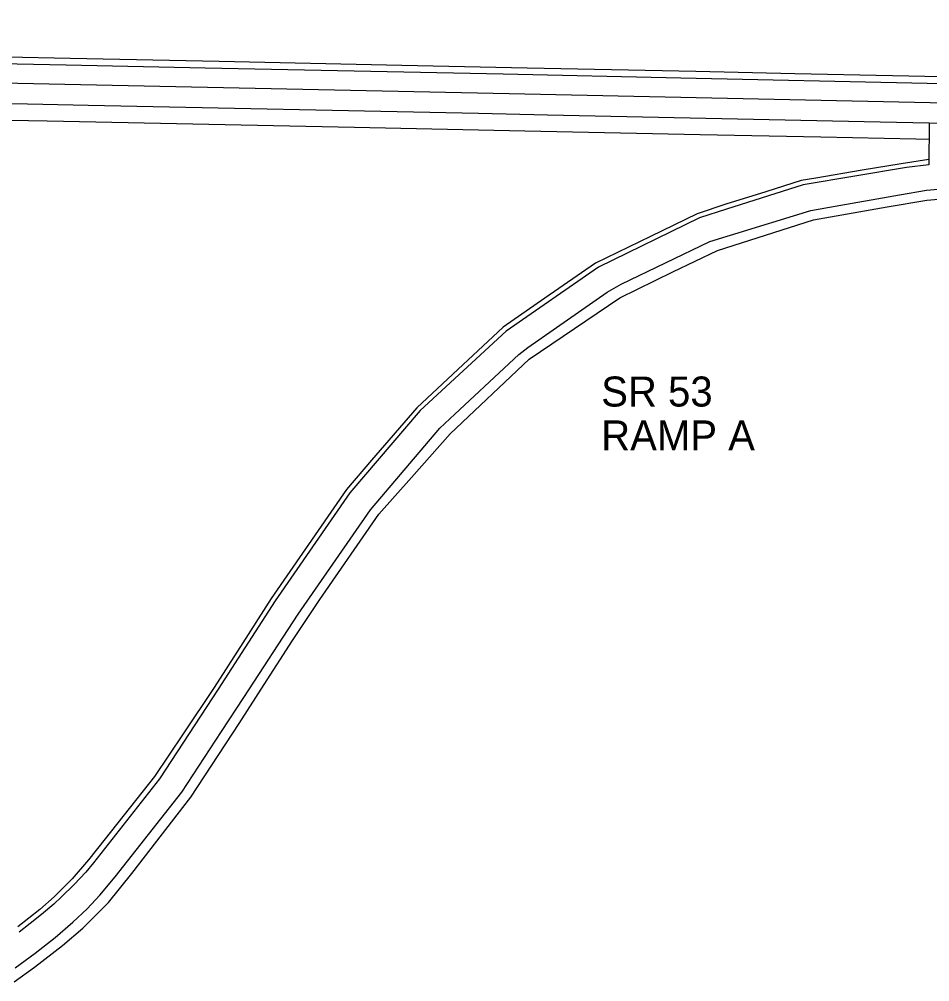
# Model space of a CAD drawing. Extents: x 1855721 to 1876784, y 662259 to 674089.
# Drawn here: x 1870534 to 1871080, y 669683 to 670260 of the extents above; entities that cross this region are included whole.
import ezdxf

# ---------------------------------------------------------------- set-up
doc = ezdxf.new("R2010")
doc.units = 0
for name, color, linetype in [('_CIVIL_CONSTRUCTION', 7, 'Continuous'), ('GE_X_Alignment_100_Bearings', 7, 'Continuous'), ('GE_X_Alignment_100_Cardinal_Points', 7, 'Continuous'), ('GE_X_Alignment_100_Curve_Data', 7, 'Continuous'), ('SC_Scratch1', 7, 'Continuous')]:
    doc.layers.add(name, color=color, linetype=linetype)

msp = doc.modelspace()

# ---------------------------------------------------------------- linework, layer by layer
at = {"layer": '_CIVIL_CONSTRUCTION'}
msp.add_line((1871080.01, 670198.03), (1871079.66, 670172.78), dxfattribs=at)
for points in [[(1870234.8, 670215.72), (1870277.14, 670214.96), (1870306.82, 670214.43), (1870547.81, 670209.13), (1870575.11, 670208.54), (1870809.46, 670203.68), (1870850.75, 670202.82), (1871050.46, 670198.65), (1871080.01, 670198.03)], [(1870531.36, 669690.95), (1870543.28, 669699.65), (1870555.2, 669709.02), (1870565.87, 669718.21), (1870574.44, 669726.36), (1870582.1, 669734.43), (1870591.38, 669745.56), (1870631.32, 669796.32), (1870655.2, 669832.74), (1870668.53, 669853.09), (1870701.24, 669903.1), (1870744.61, 669965.8), (1870786.27, 670014.74), (1870795.16, 670023.11), (1870833.58, 670058.85), (1870839, 670063.18), (1870886.58, 670096.44), (1870895.04, 670101.16), (1870948.3, 670126.73), (1870960.63, 670130.57), (1871008.85, 670145.44), (1871020.17, 670147.43), (1871062.04, 670154.79), (1871078.4, 670157.49), (1871099.34, 670159.4)]]:
    msp.add_lwpolyline(points, dxfattribs=at)
at = {"layer": 'GE_X_Alignment_100_Bearings'}
msp.add_lwpolyline([(1869304.01, 670248.74), (1869402.4, 670246.63), (1869701.27, 670239.83), (1869838.6, 670236.8), (1869901.39, 670235.7), (1870061.29, 670232.32), (1870306.95, 670226.64), (1870570.41, 670220.93), (1870827.85, 670215.6), (1871080.56, 670210.16), (1871438.65, 670202.48), (1871763.97, 670195.25), (1872009.16, 670190.02), (1872201.36, 670186.27), (1872386.22, 670182.41), (1872671.76, 670176.66)], dxfattribs=at)
at = {"layer": 'GE_X_Alignment_100_Cardinal_Points'}
msp.add_line((1871080.01, 670198.03), (1871766.97, 670183.37), dxfattribs=at)
at = {"layer": 'GE_X_Alignment_100_Curve_Data'}
for points in [[(1869312.19, 670260.13), (1869356.66, 670259.09), (1869411.58, 670257.82), (1869662.96, 670252.5), (1869704.1, 670251.62), (1869832.77, 670248.6), (1869881.61, 670247.5), (1869917.95, 670246.72), (1870016.19, 670244.73), (1870072.19, 670243.57), (1870302.52, 670238.15), (1870374.92, 670236.63), (1870561.95, 670232.73), (1870645.26, 670231.01), (1870824.17, 670227.32), (1870930.78, 670225.03), (1871078.75, 670221.85), (1871163.65, 670220.03)], [(1871079.66, 670172.78), (1871066.4, 670171.09), (1871004.21, 670160.82), (1870958.33, 670146.25), (1870942.02, 670140.99), (1870881.42, 670111.38), (1870826.01, 670072.97), (1870774.37, 670025.27), (1870732.11, 669975.85), (1870687.32, 669911.21), (1870653.21, 669858.14), (1870617.82, 669804.32), (1870578.24, 669753.91), (1870573.61, 669748.29), (1870566.78, 669740.82), (1870559.18, 669733.38), (1870554.46, 669729.1), (1870547.11, 669722.85), (1870540.37, 669717.44), (1870533.68, 669712.32)]]:
    msp.add_lwpolyline(points, dxfattribs=at)
at = {"layer": 'SC_Scratch1'}
for points in [[(1869971.04, 670249.82), (1870035.68, 670248.42), (1870088.03, 670247.25), (1870147.03, 670245.9), (1870222.18, 670244.18), (1870286.43, 670242.7), (1870374.51, 670240.81), (1870487.6, 670238.42), (1870564.28, 670236.8), (1870653.78, 670234.91), (1870763.31, 670232.61), (1870838.63, 670231.02), (1870939.83, 670228.88), (1870999.36, 670227.62), (1871057.84, 670226.39), (1871116.3, 670225.15)], [(1870234.49, 670203.93), (1870270.24, 670204.08), (1870550.58, 670199.25), (1870734.97, 670195.37), (1870837.14, 670193.22), (1870942.52, 670191.05), (1871014.97, 670189.55), (1871071.82, 670188.37), (1871079.87, 670188.21)], [(1871079.7, 670176.01), (1871063.1, 670173.39), (1871039.73, 670169.5), (1871011.79, 670164.85), (1871003.01, 670163.33), (1870981.93, 670156.65), (1870957.95, 670149.06), (1870940.59, 670143.42), (1870912.68, 670129.85), (1870879.7, 670113.81), (1870849.23, 670092.66), (1870824.17, 670075.26), (1870794.08, 670047.2), (1870772.28, 670026.88), (1870745.24, 669995.43), (1870730.11, 669977.83), (1870696.18, 669928.79), (1870684.95, 669912.54), (1870667.85, 669885.81), (1870650.73, 669859.09), (1870632.06, 669831.21), (1870614.97, 669805.66), (1870585.34, 669768.29), (1870575.28, 669755.59), (1870565.58, 669744.37), (1870554.66, 669733.56), (1870546.03, 669725.94), (1870532.92, 669715.41)], [(1870530.72, 669682.51), (1870542.96, 669691.25), (1870559.75, 669704.25), (1870571.94, 669714.72), (1870587.29, 669730.15), (1870601.33, 669747.57), (1870636.68, 669793.21), (1870665.72, 669837.43), (1870680.81, 669860.83), (1870697.74, 669887.38), (1870714.07, 669911.94), (1870749.53, 669963.04), (1870769.14, 669985.16), (1870792.43, 670011.39), (1870839.88, 670056.06), (1870894.21, 670093.01), (1870926.14, 670108.64), (1870952.81, 670121.41), (1871010.56, 670139.8), (1871054.68, 670147.51), (1871078.54, 670151.48), (1871104.2, 670153.74)]]:
    msp.add_lwpolyline(points, dxfattribs=at)

# ---------------------------------------------------------------- texts
for s, p in [('SR 53', (1870883.05, 670027.72)), ('RAMP A', (1870883.05, 670001.38))]:
    msp.add_text(s, height=18, dxfattribs=at).set_placement(p)

doc.saveas('drawing.dxf')
